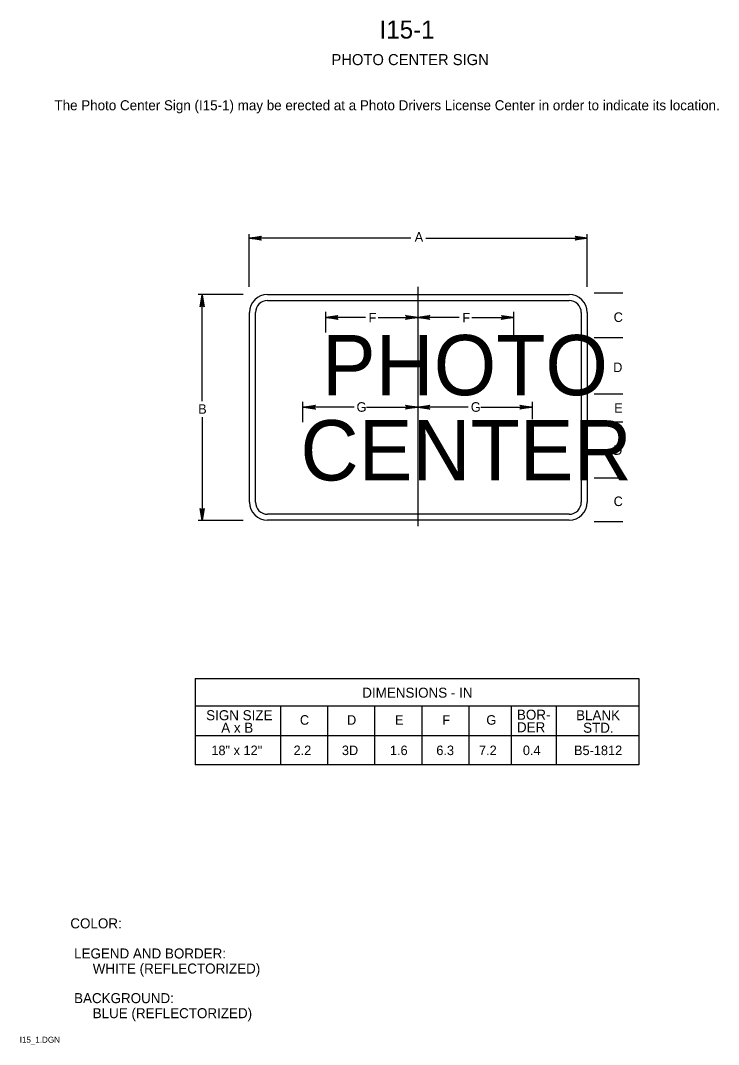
# Model space of a CAD drawing. Extents: x 0.013 to 0.187, y 0.004 to 0.259.
import ezdxf

# ---------------------------------------------------------------- set-up
doc = ezdxf.new("R2010")
doc.units = 0
for name, color, linetype in [('1', 7, 'Continuous'), ('2', 7, 'Continuous'), ('3', 7, 'Continuous'), ('5', 7, 'Continuous')]:
    doc.layers.add(name, color=color, linetype=linetype)

# ---------------------------------------------------------------- blocks, each defined once
blk = doc.blocks.new('RARROW')
at = {"layer": '3'}
for p, q in [((-2.156, 0.285), (-2.2665, 0.384625)), ((-2.2665, 0.384625), (0, 0)), ((0, 0), (-2.2665, -0.379125)), ((-2.156, 0.285), (-2.075625, 0.12075)), ((0, 0), (-2.156, 0.285)), ((-2.14975, -0.2705), (0, 0)), ((-2.075625, 0.12075), (0, 0)), ((0, 0), (-2.074, -0.108)), ((-2.2665, -0.379125), (-2.14975, -0.2705)), ((-2.074, -0.108), (-2.14975, -0.2705))]:
    blk.add_line(p, q, dxfattribs=at)

msp = doc.modelspace()

# ---------------------------------------------------------------- linework, layer by layer
at = {"layer": '1'}
for p, q in [((0.11188, 0.13312), (0.11188, 0.19275)), ((0.15575, 0.19125), (0.16287, 0.19125)), ((0.15575, 0.18013), (0.16287, 0.18013)), ((0.15575, 0.16612), (0.16287, 0.16612)), ((0.15575, 0.15913), (0.16287, 0.15913)), ((0.15575, 0.14513), (0.16287, 0.14513)), ((0.15575, 0.13425), (0.16287, 0.13425))]:
    msp.add_line(p, q, dxfattribs=at)
at = {"layer": '3'}
for p, q in [((0.06975, 0.19275), (0.06975, 0.20588)), ((0.11, 0.20488), (0.06975, 0.20488)), ((0.11375, 0.20488), (0.154, 0.20488)), ((0.154, 0.19275), (0.154, 0.20588)), ((0.06825, 0.19083), (0.05704, 0.19083)), ((0.058, 0.16425), (0.058, 0.19083)), ((0.07429, 0.19083), (0.14954, 0.19083)), ((0.07429, 0.18933), (0.14954, 0.18933)), ((0.06979, 0.13908), (0.06979, 0.18633)), ((0.07129, 0.13908), (0.07129, 0.18633)), ((0.08887, 0.18138), (0.08887, 0.1865)), ((0.11188, 0.18438), (0.11188, 0.1865)), ((0.13575, 0.18063), (0.13575, 0.1865)), ((0.15254, 0.18633), (0.15254, 0.13908)), ((0.15404, 0.18633), (0.15404, 0.13908)), ((0.09875, 0.18513), (0.08887, 0.18513)), ((0.10188, 0.18513), (0.11175, 0.18513)), ((0.12212, 0.18513), (0.11175, 0.18513)), ((0.12525, 0.18513), (0.13575, 0.18513)), ((0.08313, 0.159), (0.08313, 0.16412)), ((0.11188, 0.15913), (0.11188, 0.16412)), ((0.14037, 0.15975), (0.14037, 0.16412)), ((0.09588, 0.16275), (0.08325, 0.16275)), ((0.099, 0.16275), (0.11175, 0.16275)), ((0.12437, 0.16275), (0.11175, 0.16275)), ((0.1275, 0.16275), (0.14037, 0.16275)), ((0.058, 0.16025), (0.058, 0.1345)), ((0.14954, 0.13608), (0.07429, 0.13608)), ((0.06824, 0.1345), (0.05704, 0.1345)), ((0.14954, 0.13458), (0.07429, 0.13458)), ((0.05625, 0.09513), (0.16687, 0.09513)), ((0.05625, 0.09513), (0.05625, 0.07362)), ((0.16687, 0.09513), (0.16687, 0.07362)), ((0.16687, 0.08825), (0.05625, 0.08825)), ((0.07754, 0.08828), (0.07754, 0.07366)), ((0.08925, 0.08825), (0.08925, 0.07362)), ((0.101, 0.08825), (0.101, 0.07362)), ((0.11275, 0.08825), (0.11275, 0.07362)), ((0.1245, 0.08825), (0.1245, 0.07362)), ((0.13504, 0.08828), (0.13504, 0.07366)), ((0.14629, 0.08828), (0.14629, 0.07366)), ((0.16687, 0.08088), (0.05625, 0.08088)), ((0.16687, 0.07362), (0.05625, 0.07362))]:
    msp.add_line(p, q, dxfattribs=at)
for centre, radius, start, end in [((0.07429, 0.18633), 0.0045, 90, 180), ((0.07429, 0.18633), 0.003, 90, 180), ((0.14954, 0.18633), 0.0045, 0, 90), ((0.14954, 0.18633), 0.003, 0, 90), ((0.07429, 0.13908), 0.0045, 180, 270), ((0.07429, 0.13908), 0.003, 180, 270), ((0.14954, 0.13908), 0.0045, 270, 0), ((0.14954, 0.13908), 0.003, 270, 0)]:
    msp.add_arc(centre, radius, start, end, dxfattribs=at)

# ---------------------------------------------------------------- block references
at = {"layer": '3', "xscale": 0.0013236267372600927, "yscale": 0.001309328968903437}
for p, rotation in [((0.06975, 0.20488), 180), ((0.058, 0.19075), 90), ((0.08887, 0.18513), 180), ((0.11175, 0.18513), 180), ((0.08325, 0.16275), 180), ((0.11175, 0.16275), 180), ((0.058, 0.1345), -90)]:
    msp.add_blockref('RARROW', p, dxfattribs=dict(at, rotation=rotation))
for p in [(0.154, 0.20488), (0.11175, 0.18513), (0.13562, 0.18513), (0.11175, 0.16275), (0.14025, 0.16275)]:
    msp.add_blockref('RARROW', p, dxfattribs=at)

# ---------------------------------------------------------------- texts
at = {"layer": '1'}
for s, height, p in [('I15-1', 0.0045, (0.10225, 0.25462)), ('PHOTO CENTER SIGN', 0.0027503, (0.09025, 0.248)), ('PHOTO', 0.014999, (0.08788, 0.16575)), ('E', 0.00238, (0.16075, 0.16137)), ('CENTER', 0.015032, (0.0825, 0.1445)), ('COLOR:', 0.0025, (0.02513, 0.03288)), (' LEGEND AND BORDER:', 0.0024998, (0.02513, 0.02538)), ('      WHITE (REFLECTORIZED)', 0.0024998, (0.02513, 0.02163)), (' BACKGROUND:', 0.0024998, (0.02513, 0.01425)), ('      BLUE (REFLECTORIZED)', 0.0024998, (0.02513, 0.0105)), ('I15_1.DGN', 0.0015, (0.0125, 0.00438))]:
    msp.add_text(s, height=height, dxfattribs=at).set_placement(p)
at = {"layer": '2'}
msp.add_text('   The Photo Center Sign (I15-1) may be erected at a Photo Drivers License Center in order to indicate its location.', height=0.00249975, dxfattribs=at).set_placement((0.01837, 0.23675))
at = {"layer": '3'}
for s, height, p in [('A', 0.00238, (0.111, 0.204)), ('F', 0.00238, (0.0995, 0.18388)), ('F', 0.00238, (0.12287, 0.18388)), ('B', 0.00238, (0.057, 0.16112)), ('G', 0.00238, (0.0965, 0.16162)), ('G', 0.00238, (0.125, 0.16162)), ('DIMENSIONS - IN', 0.0024998, (0.09793, 0.09037)), ('SIGN SIZE', 0.0025, (0.059, 0.08475)), ('BOR-', 0.0025, (0.1365, 0.08488)), ('BLANK', 0.0025, (0.15125, 0.08475)), ('C', 0.00238, (0.08238, 0.08363)), ('D', 0.00238, (0.09413, 0.08363)), ('E', 0.00238, (0.10612, 0.08363)), ('F', 0.00238, (0.11788, 0.08363)), ('G', 0.00238, (0.12887, 0.08363)), ('DER', 0.0025, (0.1365, 0.08175)), ('A x B', 0.0025, (0.06275, 0.08163)), ('STD.', 0.0025, (0.153, 0.08163)), ('18" x 12"', 0.002375, (0.0603, 0.07606)), ('2.2', 0.002375, (0.08079, 0.07606)), ('3D', 0.002375, (0.09285, 0.07606)), ('1.6', 0.002375, (0.10483, 0.07606)), ('6.3', 0.002375, (0.1164, 0.07606)), ('7.2', 0.002375, (0.12704, 0.07606)), ('0.4', 0.002375, (0.13798, 0.07606)), ('B5-1812', 0.002375, (0.15074, 0.07606))]:
    msp.add_text(s, height=height, dxfattribs=at).set_placement(p)
at = {"layer": '5'}
for s, p in [('C', (0.16062, 0.184)), ('D', (0.1605, 0.1715)), ('D', (0.1605, 0.15088)), ('C', (0.16062, 0.13812))]:
    msp.add_text(s, height=0.00238, dxfattribs=at).set_placement(p)

doc.saveas('drawing.dxf')
